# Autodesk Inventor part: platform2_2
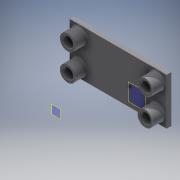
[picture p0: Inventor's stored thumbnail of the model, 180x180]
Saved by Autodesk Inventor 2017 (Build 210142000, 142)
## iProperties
Created: 2017-05
Part Number: platform2_2
Material: Generic
Document SubType Name: Modeling
Designer: 1717440
Density: 1 g/cm^3
Appearance: Default
Author: 1717440
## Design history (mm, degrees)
workplane "Work Plane1"
workplane "Work Plane4"
workplane "Work Plane2"
workplane "Work Plane3"
sketch "Sketch2"
  geometry: L1 (38.448, -43.362)-(38.448, 16.638); L2 (-86.552, 16.638)-(-86.552, -43.362); L3 (38.448, 16.638)-(-86.552, -43.362); L4 (-86.552, 16.638)-(38.448, -43.362); L5 (38.448, -43.362)-(-86.552, -43.362); L6 (38.448, 16.638)-(-86.552, 16.638); L7 (-25.603, -14.224)-(-22.5, -14.224); L8 (-22.5, -14.224)-(-22.5, -12.5); L9 (-22.5, -12.5)-(-25.603, -12.5); L10 (-25.603, -12.5)-(-25.603, -14.224); L11 (-22.5, -14.224)-(-25.603, -12.5); 2 further points
  constraints: 22 end point, 3 horizontal, 3 perpendicular, 2 midpoint, 2 parallel
  dimensions: "d11" = 125 distance of L1.start L2.end; "d12" = 60 distance of L2.start L2.end
extrude "Extrusion7" join sketch "Sketch2" distance "d20" = 6; taper "d21" = 0 deg
workplane "Work Plane5"
sketch "Sketch7"
  geometry: L1 (38.448, 43.362)-(38.448, -16.638) reference; L2 (-86.552, 43.362)-(38.448, 43.362) reference; L3 (-86.552, -16.638)-(-86.552, 43.362) reference; L4 (38.448, -16.638)-(-86.552, -16.638) reference; L5 (-74.052, 30.862)-(25.948, 30.862); L6 (25.948, 30.862)-(25.948, -4.138); L7 (25.948, -4.138)-(-74.052, -4.138); L8 (-74.052, -4.138)-(-74.052, 30.862); C1 r 6.425 at (-74.052, 30.862); C2 r 6.425 at (25.948, -4.138); C3 r 6.425 at (-74.052, -4.138); C4 r 6.425 at (25.948, 30.862); C5 r 10 at (-74.052, -4.138); C6 r 10 at (-74.052, 30.862); C7 r 10 at (25.948, 30.862); C8 r 10 at (25.948, -4.138); 1 further point
  constraints: 9 coincident, 8 centre point, 8 end point, 1 point on line, 3 other
  dimensions: "d25" = 12.5 distance between parallel lines of L3 L8; "d26" = 12.85 diameter of C1 (= d28); "d27" = 12.85 diameter of C2 (= d28); "d28" = 12.85 diameter of C3; "d29" = 12.85 diameter of C4 (= d28); "d33" = 20 diameter of C5; "d34" = 20 diameter of C6; "d35" = 20 diameter of C7; "d36" = 20 diameter of C8
workplane "Work Plane6"
extrude "Extrusion10" join sketch "Sketch7" distance "d37" = 15; taper "d38" = 0 deg
fillet "Fillet3" dims "d39" = 2
fillet "Fillet4" dims "d40" = 1
sketch "Sketch8"
  geometry: C1 r 2.72 at (-8.733, -5.862); 2 further points
  constraints: 1 centre point, 1 coincident
extrude "Extrusion11" cut sketch "Sketch8" distance "d41" = 16; taper "d42" = 0 deg
body "Solid1"
node "Reference6"
